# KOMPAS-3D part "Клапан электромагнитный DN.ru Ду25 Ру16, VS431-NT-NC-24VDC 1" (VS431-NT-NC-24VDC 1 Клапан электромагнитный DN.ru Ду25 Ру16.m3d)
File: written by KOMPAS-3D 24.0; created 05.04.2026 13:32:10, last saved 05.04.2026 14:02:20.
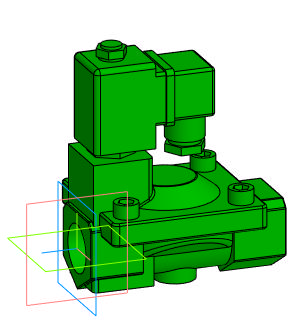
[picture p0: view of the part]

Document properties: Автор: artio; Полное имя файла: C:\Users\artio\OneDrive\Рабочий стол\Клапан электромагнитный DN.ru\VS431\VS431-NT-NC\VS431-NT-NC-24VDC\Ду25\VS431-NT-NC-24VDC 1 Клапан электромагнитный DN.ru Ду25 Ру16.m3d

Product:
- Body: Тело 1  | qty 1
    Масса: 1.729172
- Part/product: Клапан электромагнитный DN.ru Ду25 Ру16  | designation VS431-NT-NC-24VDC 1
    Масса: 1.267
    Раздел спецификации: Прочие изделия
    Примечание: D130-04749
    additional columns: ef56311e-7521-43dc-8291-0e6108b3d81d; artio; c; Шероховатость не задана; Да

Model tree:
1. Операция без истории:1

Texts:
  VS431-NT-NC-24VDC 1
